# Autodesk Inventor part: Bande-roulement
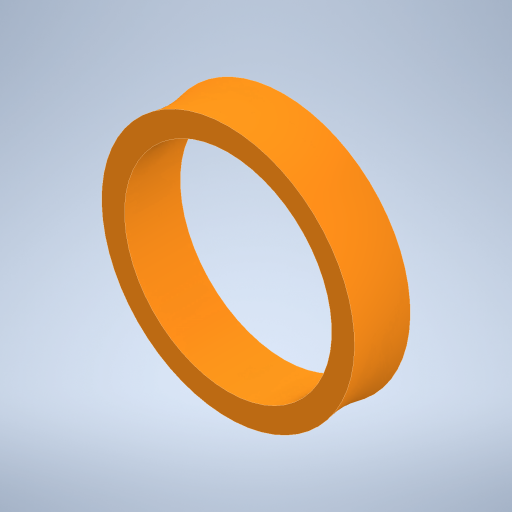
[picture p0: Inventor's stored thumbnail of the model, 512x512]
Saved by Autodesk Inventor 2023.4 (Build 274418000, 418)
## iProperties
Created: 2025-03
Part Number: Bande-roulement
Material: Générique
Document SubType Name: Modeling
Designer: bruno
Density: 1 g/cm^3
Appearance: Orange
Author: bruno
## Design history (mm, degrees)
sketch "Esquisse1"
  geometry: L1 (0, 0)-(0, -282.236); L2 (158.65, -94.628)-(130, -94.628); L3 (130, -94.628)-(130, -164.628); L4 (130, -164.628)-(158.65, -164.628); A1 r 152.152 centre (306.722, -129.628) between (158.65, -94.628) and (158.65, -164.628); 2 further points
  constraints: 8 end point, 2 midpoint, 2 point on circle, 1 centre point, 1 horizontal, 1 parallel, 1 perpendicular, 1 vertical
  dimensions: "d0" = 130 distance between parallel lines of L1 L3; "d3" = 70 distance of point (144.325, -164.628) point (144.325, -94.628)
revolve "Révolution1" sketch "Esquisse1" stored, may be unused: angle "d2" = 90 deg
node "Solide1"
